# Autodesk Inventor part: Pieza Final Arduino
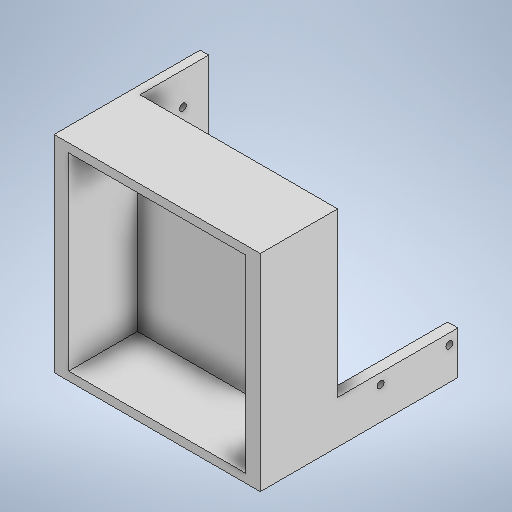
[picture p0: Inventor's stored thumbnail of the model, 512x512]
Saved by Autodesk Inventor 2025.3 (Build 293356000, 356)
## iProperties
Created: 2025-11
Part Number: Pieza Final Arduino
Material: Genérico
Document SubType Name: Modeling
Designer: Dell
Density: 1 g/cm^3
Appearance: Valor por defecto
Author: Dell
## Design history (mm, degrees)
sketch "Boceto1"
  geometry: L1 (-120, 0)-(120, 0); L2 (120, 0)-(120, 240); L3 (120, 240)-(-120, 240); L4 (-120, 240)-(-120, 0); 1 further point
  constraints: 8 end point, 2 perpendicular, 1 horizontal, 1 midpoint, 1 vertical
  dimensions: "d0" = 240 distance of L1.start L1.end; "d1" = 240 distance of L1.end L2.end
extrude "Extrusión1" new body sketch "Boceto1" distance "d2" = 10; taper "d3" = 0 deg
sketch "Boceto2"
  geometry: L1 (-120, 0)-(120, 0) reference; L2 (-120, 240)-(-120, 0) reference; L3 (120, 240)-(-120, 240) reference; L4 (-120, 240)-(-103, 240); L5 (120, 240)-(103, 240); L6 (120, 0)-(103, 0); L7 (103, 10)-(-103, 10); L8 (120, 0)-(120, 240) reference; L9 (103, 10)-(103, 180); L10 (-103, 10)-(-103, 180); L11 (-120, 240)-(-103, 240); L12 (-103, 230)-(-103, 180); L13 (-103, 230)-(103, 230); L14 (103, 230)-(103, 180); 1 further point
  constraints: 20 end point, 3 point on line, 2 horizontal, 1 collinear, 1 parallel
extrude "Extrusión2" join sketch "Boceto2" distance "d11" = 80; taper "d12" = 0 deg
sketch "Boceto3"
  geometry: L1 (120, 240)-(120, 0) reference; L2 (120, 0)-(110, 0); L3 (120, 0)-(-120, 0) reference; L4 (110, 0)-(110, 240); L5 (-120, 240)-(120, 240) reference; L6 (120, 240)-(120, 0); L7 (-120, 0)-(-120, 240) reference; L8 (-120, 220)-(-120, 240); L9 (-103, 240)-(-120, 240); L10 (-120, 0)-(-108.5, 0); L11 (-103, 230)-(-103, 10) reference; L12 (-120, 0)-(-114.25, 0); L13 (-120, 40)-(-120, 0); L14 (-120, 0)-(-114.25, 0); L15 (-108, 40)-(-108, 0); L16 (-120, 0)-(-108, 0); L17 (-120, 0)-(-120, 40); L18 (-108, 40)-(-108, 50); L19 (-108, 50)-(-120, 50); L20 (-120, 40)-(-120, 50); 3 further points
  constraints: 30 end point, 9 point on line, 6 collinear, 3 perpendicular, 1 midpoint, 1 parallel, 1 vertical
  dimensions: "d13" = 10 distance of L1.end L2.end
extrude "Extrusión5" join sketch "Boceto3" distance "d21" = 80; taper "d22" = 0 deg
extrude "Extrusión6" join sketch "Boceto3" distance "d23" = 140; taper "d24" = 0 deg
sketch "Boceto4"
  geometry: L1 (80, 240)-(80, 0) reference; C1 r 4.1 at (50, 37.5); C2 r 4.1 at (50, 202.5); 2 further points
  constraints: 2 centre point
  dimensions: "d62" = 8.2 diameter of C1
extrude "Extrusión7" cut sketch "Boceto4" distance "d29" = 10; taper "d30" = 0 deg
sketch "Boceto5"
  geometry: L1 (0, 0)-(0, 240) reference; L2 (0, 20)-(50, 20); L3 (0, 50)-(-140, 50) reference; L4 (0, 50)-(-140, 50) reference; C1 r 4.1 at (-50, 38); C2 r 4.1 at (-130, 38)
  constraints: 2 centre point, 2 end point, 1 horizontal, 1 point on line
  dimensions: "d51" = 8.2 diameter of C1; "d56" = 8.2 diameter of C2
extrude "Extrusión8" cut sketch "Boceto5" distance "d44" = 12; taper "d45" = 0 deg
feature "Rosca1" dims "d53" = 80, "d54" = 0
extrude "Extrusión9" cut sketch "Boceto5" distance "d57" = 12; taper "d58" = 0 deg
feature "Rosca2" dims "d59" = 80, "d60" = 0
feature "Rosca3" dims "d64" = 80, "d65" = 0
feature "Rosca4" dims "d66" = 80, "d67" = 0
feature "Rosca5" dims "d68" = 80, "d69" = 0
node "Sólido1"
